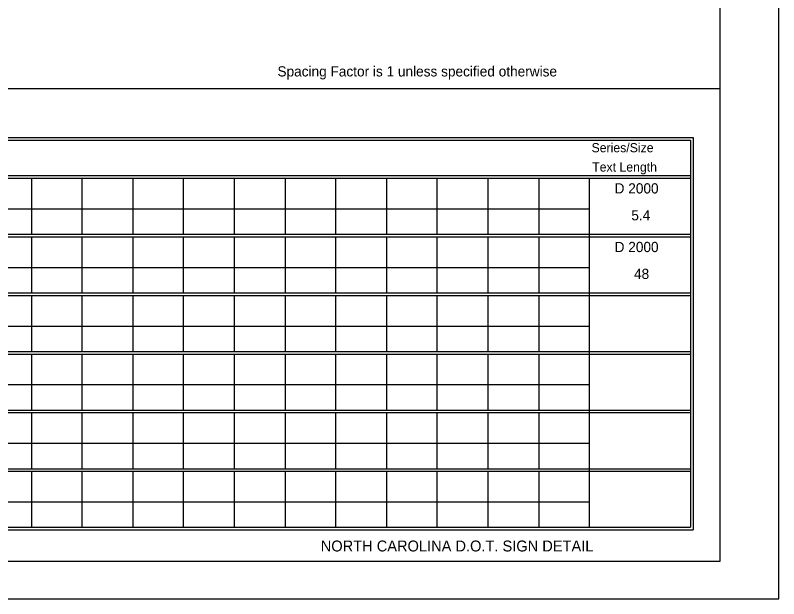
# Model space of a CAD drawing. Extents: x 1708.4 to 1771.6, y 238.3 to 283.4.
# Drawn here: x 1757.88 to 1771.63, y 238.25 to 248.76 of the extents above; entities that cross this region are included whole.
import ezdxf

# ---------------------------------------------------------------- set-up
doc = ezdxf.new("R2010")
doc.units = 0
doc.layers.add('Level 6', color=7, linetype='Continuous')
doc.layers.add('Level 9', color=7, linetype='Continuous')

msp = doc.modelspace()

# ---------------------------------------------------------------- linework, layer by layer
at = {"layer": 'Level 6'}
for p, q in [((1753.415, 247.445), (1770.57, 247.445)), ((1742.622, 245.873), (1764.388, 245.873)), ((1742.622, 245.827), (1764.388, 245.827)), ((1758.168, 245.827), (1758.168, 244.817)), ((1759.076, 245.827), (1759.076, 244.817)), ((1759.994, 245.827), (1759.994, 244.817)), ((1760.903, 245.827), (1760.903, 244.817)), ((1761.82, 245.827), (1761.82, 244.817)), ((1762.738, 245.827), (1762.738, 244.817)), ((1763.414, 245.873), (1770.043, 245.873)), ((1763.414, 245.827), (1770.043, 245.827)), ((1763.647, 245.827), (1763.647, 244.817)), ((1763.647, 245.827), (1763.647, 244.817)), ((1764.564, 245.827), (1764.564, 244.817)), ((1765.473, 245.827), (1765.473, 244.817)), ((1766.391, 245.827), (1766.391, 244.817)), ((1767.308, 245.827), (1767.308, 244.817)), ((1768.217, 245.827), (1768.217, 239.606)), ((1743.539, 245.276), (1764.388, 245.276)), ((1763.414, 245.276), (1768.217, 245.276)), ((1768.217, 245.067), (1768.217, 244.817)), ((1742.622, 244.817), (1764.388, 244.817)), ((1763.414, 244.817), (1770.043, 244.817)), ((1742.622, 244.771), (1764.388, 244.771)), ((1758.168, 244.771), (1758.168, 243.761)), ((1759.076, 244.771), (1759.076, 243.761)), ((1759.994, 244.771), (1759.994, 243.761)), ((1760.903, 244.771), (1760.903, 243.761)), ((1761.82, 244.771), (1761.82, 243.761)), ((1762.738, 244.771), (1762.738, 243.761)), ((1763.414, 244.771), (1770.043, 244.771)), ((1763.647, 244.771), (1763.647, 243.761)), ((1763.647, 244.771), (1763.647, 243.761)), ((1764.564, 244.771), (1764.564, 243.761)), ((1765.473, 244.771), (1765.473, 243.761)), ((1766.391, 244.771), (1766.391, 243.761)), ((1767.308, 244.771), (1767.308, 243.761)), ((1768.217, 244.771), (1768.217, 244.292)), ((1743.539, 244.22), (1764.388, 244.22)), ((1763.414, 244.22), (1768.217, 244.22)), ((1768.217, 244.09), (1768.217, 243.761)), ((1742.622, 243.761), (1764.388, 243.761)), ((1742.622, 243.715), (1764.388, 243.715)), ((1758.168, 243.715), (1758.168, 242.705)), ((1759.076, 243.715), (1759.076, 242.705)), ((1759.994, 243.715), (1759.994, 242.705)), ((1760.903, 243.715), (1760.903, 242.705)), ((1761.82, 243.715), (1761.82, 242.705)), ((1762.738, 243.715), (1762.738, 242.705)), ((1763.414, 243.761), (1770.043, 243.761)), ((1763.414, 243.715), (1770.043, 243.715)), ((1763.647, 243.715), (1763.647, 242.705)), ((1763.647, 243.715), (1763.647, 242.705)), ((1764.564, 243.715), (1764.564, 242.705)), ((1765.473, 243.715), (1765.473, 242.705)), ((1766.391, 243.715), (1766.391, 242.705)), ((1767.308, 243.715), (1767.308, 242.705)), ((1768.217, 243.715), (1768.217, 243.305)), ((1743.539, 243.164), (1764.388, 243.164)), ((1763.414, 243.164), (1768.217, 243.164)), ((1768.217, 243.003), (1768.217, 242.705)), ((1742.622, 242.705), (1764.388, 242.705)), ((1742.622, 242.659), (1764.388, 242.659)), ((1758.168, 242.659), (1758.168, 241.649)), ((1759.076, 242.659), (1759.076, 241.649)), ((1759.994, 242.659), (1759.994, 241.649)), ((1760.903, 242.659), (1760.903, 241.649)), ((1761.82, 242.659), (1761.82, 241.649)), ((1762.738, 242.659), (1762.738, 241.649)), ((1763.414, 242.705), (1770.043, 242.705)), ((1763.414, 242.659), (1770.043, 242.659)), ((1763.647, 242.659), (1763.647, 241.649)), ((1763.647, 242.659), (1763.647, 241.649)), ((1764.564, 242.659), (1764.564, 241.649)), ((1765.473, 242.659), (1765.473, 241.649)), ((1766.391, 242.659), (1766.391, 241.649)), ((1767.308, 242.659), (1767.308, 241.649)), ((1768.217, 242.659), (1768.217, 242.217)), ((1743.539, 242.108), (1764.388, 242.108)), ((1763.414, 242.108), (1768.217, 242.108)), ((1768.217, 241.915), (1768.217, 241.649)), ((1742.622, 241.649), (1764.388, 241.649)), ((1742.622, 241.649), (1764.388, 241.649)), ((1758.168, 241.767), (1758.168, 241.649)), ((1759.076, 241.767), (1759.076, 241.649)), ((1759.994, 241.767), (1759.994, 241.649)), ((1760.903, 241.767), (1760.903, 241.649)), ((1761.82, 241.767), (1761.82, 241.649)), ((1762.738, 241.767), (1762.738, 241.649)), ((1763.414, 241.649), (1770.043, 241.649)), ((1763.414, 241.649), (1770.043, 241.649)), ((1763.647, 241.767), (1763.647, 241.649)), ((1763.647, 241.767), (1763.647, 241.649)), ((1764.564, 241.767), (1764.564, 241.649)), ((1765.473, 241.767), (1765.473, 241.649)), ((1766.391, 241.767), (1766.391, 241.649)), ((1767.308, 241.767), (1767.308, 241.649)), ((1768.217, 241.767), (1768.217, 241.649)), ((1742.622, 241.603), (1764.388, 241.603)), ((1742.622, 241.603), (1764.388, 241.603)), ((1758.168, 241.603), (1758.168, 240.659)), ((1758.168, 241.603), (1758.168, 240.593)), ((1759.076, 241.603), (1759.076, 240.659)), ((1759.076, 241.603), (1759.076, 240.593)), ((1759.994, 241.603), (1759.994, 240.659)), ((1759.994, 241.603), (1759.994, 240.593)), ((1760.903, 241.603), (1760.903, 240.659)), ((1760.903, 241.603), (1760.903, 240.593)), ((1761.82, 241.603), (1761.82, 240.659)), ((1761.82, 241.603), (1761.82, 240.593)), ((1762.738, 241.603), (1762.738, 240.659)), ((1762.738, 241.603), (1762.738, 240.593)), ((1763.414, 241.603), (1770.043, 241.603)), ((1763.414, 241.603), (1770.043, 241.603)), ((1763.647, 241.603), (1763.647, 240.659)), ((1763.647, 241.603), (1763.647, 240.593)), ((1763.647, 241.603), (1763.647, 240.659)), ((1763.647, 241.603), (1763.647, 240.593)), ((1764.564, 241.603), (1764.564, 240.659)), ((1764.564, 241.603), (1764.564, 240.593)), ((1765.473, 241.603), (1765.473, 240.659)), ((1765.473, 241.603), (1765.473, 240.593)), ((1766.391, 241.603), (1766.391, 240.659)), ((1766.391, 241.603), (1766.391, 240.593)), ((1767.308, 241.603), (1767.308, 240.659)), ((1767.308, 241.603), (1767.308, 240.593)), ((1768.217, 241.603), (1768.217, 241.149)), ((1768.217, 241.603), (1768.217, 241.149)), ((1743.539, 241.052), (1764.388, 241.052)), ((1743.539, 241.052), (1764.388, 241.052)), ((1763.414, 241.052), (1768.217, 241.052)), ((1763.414, 241.052), (1767.979, 241.052)), ((1768.217, 240.887), (1768.217, 240.659)), ((1768.217, 240.887), (1768.217, 240.593)), ((1758.168, 240.711), (1758.168, 240.593)), ((1759.076, 240.711), (1759.076, 240.593)), ((1759.994, 240.711), (1759.994, 240.593)), ((1760.903, 240.711), (1760.903, 240.593)), ((1761.82, 240.711), (1761.82, 240.593)), ((1762.738, 240.711), (1762.738, 240.593)), ((1763.647, 240.711), (1763.647, 240.593)), ((1763.647, 240.711), (1763.647, 240.593)), ((1764.564, 240.711), (1764.564, 240.593)), ((1765.473, 240.711), (1765.473, 240.593)), ((1766.391, 240.711), (1766.391, 240.593)), ((1767.308, 240.711), (1767.308, 240.593)), ((1768.217, 240.711), (1768.217, 240.593)), ((1742.622, 240.593), (1764.388, 240.593)), ((1742.622, 240.593), (1764.388, 240.593)), ((1742.622, 240.547), (1764.388, 240.547)), ((1742.622, 240.547), (1764.388, 240.547)), ((1758.168, 240.547), (1758.168, 239.537)), ((1758.168, 240.547), (1758.168, 239.537)), ((1759.076, 240.547), (1759.076, 239.537)), ((1759.076, 240.547), (1759.076, 239.537)), ((1759.994, 240.547), (1759.994, 239.537)), ((1759.994, 240.547), (1759.994, 239.537)), ((1760.903, 240.547), (1760.903, 239.537)), ((1760.903, 240.547), (1760.903, 239.537)), ((1761.82, 240.547), (1761.82, 239.537)), ((1761.82, 240.547), (1761.82, 239.537)), ((1762.738, 240.547), (1762.738, 239.537)), ((1762.738, 240.547), (1762.738, 239.537)), ((1763.414, 240.593), (1770.043, 240.593)), ((1763.414, 240.593), (1770.043, 240.593)), ((1763.414, 240.547), (1770.043, 240.547)), ((1763.414, 240.547), (1770.043, 240.547)), ((1763.647, 240.547), (1763.647, 239.537)), ((1763.647, 240.547), (1763.647, 239.537)), ((1763.647, 240.547), (1763.647, 239.537)), ((1763.647, 240.547), (1763.647, 239.537)), ((1764.564, 240.547), (1764.564, 239.537)), ((1764.564, 240.547), (1764.564, 239.537)), ((1765.473, 240.547), (1765.473, 239.537)), ((1765.473, 240.547), (1765.473, 239.537)), ((1766.391, 240.547), (1766.391, 239.537)), ((1766.391, 240.547), (1766.391, 239.537)), ((1767.308, 240.547), (1767.308, 239.537)), ((1767.308, 240.547), (1767.308, 239.537)), ((1768.217, 240.547), (1768.217, 240.122)), ((1768.217, 240.547), (1768.217, 240.122)), ((1743.539, 239.996), (1764.388, 239.996)), ((1743.539, 239.996), (1764.388, 239.996)), ((1763.414, 239.996), (1768.217, 239.996)), ((1763.414, 239.996), (1768.041, 239.996)), ((1768.217, 239.8), (1768.217, 239.537)), ((1768.217, 239.8), (1768.217, 239.537)), ((1742.575, 239.492), (1764.388, 239.492)), ((1742.622, 239.537), (1764.388, 239.537)), ((1742.622, 239.537), (1764.388, 239.537)), ((1742.622, 239.492), (1764.388, 239.492)), ((1763.414, 239.537), (1770.043, 239.537)), ((1763.414, 239.537), (1770.043, 239.537)), ((1763.414, 239.492), (1770.09, 239.492)), ((1763.414, 239.492), (1770.043, 239.492))]:
    msp.add_line(p, q, dxfattribs=at)
msp.add_lwpolyline([(1742.258, 258.58), (1770.57, 258.58), (1770.57, 238.923), (1742.258, 238.923)], close=True, dxfattribs=at)
for points in [[(1742.575, 240.659), (1742.575, 246.561), (1764.388, 246.561)], [(1742.622, 240.659), (1742.622, 246.515), (1764.388, 246.515)], [(1763.414, 246.561), (1770.09, 246.561), (1770.09, 240.659)], [(1763.414, 246.515), (1770.043, 246.515), (1770.043, 240.659)], [(1770.043, 241.767), (1770.043, 239.537)], [(1770.09, 241.767), (1770.09, 239.492)]]:
    msp.add_lwpolyline(points, dxfattribs=at)
at = {"layer": 'Level 9'}
msp.add_lwpolyline([(1741.568, 238.25), (1771.63, 238.25), (1771.63, 259.274), (1741.568, 259.274)], close=True, dxfattribs=at)

# ---------------------------------------------------------------- texts
at = {"layer": 'Level 6'}
for s, height, p in [('Spacing Factor is 1 unless specified otherwise', 0.18363, (1762.6, 247.66)), ('Series/Size', 0.16527, (1768.258, 246.294)), ('Text Length', 0.16527, (1768.27, 245.946)), ('NORTH CAROLINA D.O.T. SIGN DETAIL', 0.19675, (1763.38, 239.102))]:
    msp.add_text(s, height=height, rotation=360, dxfattribs=at).set_placement(p)
for s, p in [('D 2000', (1768.674, 245.552)), ('5.4', (1768.975, 245.067)), ('D 2000', (1768.674, 244.496)), ('48', (1769.023, 244.011))]:
    msp.add_text(s, height=0.1836, dxfattribs=at).set_placement(p)

doc.saveas('drawing.dxf')
